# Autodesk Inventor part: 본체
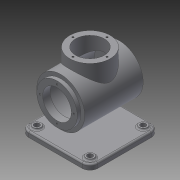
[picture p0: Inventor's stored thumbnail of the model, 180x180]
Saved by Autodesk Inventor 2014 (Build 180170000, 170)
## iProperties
Created: 2015-07
Part Number: 본체
Material: 일반
Document SubType Name: Modeling
Designer: basic
Density: 1 g/cm^3
Appearance: 기본값
Author: basic
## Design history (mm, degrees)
sketch "스케치1"
  geometry: L1 (-65, 65)-(65, 65); L2 (65, 65)-(65, -65); L3 (65, -65)-(-65, -65); L4 (-65, -65)-(-65, 65); L5 (-65, 65)-(65, -65); 2 further points
  constraints: 10 end point, 2 parallel, 1 coincident, 1 horizontal, 1 midpoint, 1 perpendicular
  dimensions: "d0" = 130 distance of L1.start L1.end; "d1" = 130 distance of L1.end L2.end
extrude "돌출1" new body sketch "스케치1" distance "d2" = 10; taper "d3" = 0 deg
fillet "모깎기1" dims "d4" = 15
fillet "모깎기2" dims "d5" = 3
sketch "스케치2"
  geometry: C1 r 7.5 at (-50, 50); 1 further point
  constraints: 1 centre point
  dimensions: "d6" = 50 horizontal distance of point (0, 0) C1.centre; "d7" = 50 horizontal distance of C1.centre point (0, 0); "d8" = 15 diameter of C1
extrude "돌출2" join sketch "스케치2" distance "d9" = 3; taper "d10" = 0 deg
sketch "스케치3"
  geometry: C1 r 7.5 at (0, 0) reference; C2 r 5 at (0, 0); 1 further point
  constraints: 1 centre point, 1 coincident
  dimensions: "d11" = 10 diameter of C2
extrude "돌출3" cut sketch "스케치3" stored distance "d12" = 3; taper "d13" = 0 deg
fillet "모깎기3" dims "d14" = 3
sketch "스케치4"
  geometry: L1 (-62, 10)-(62, 10) reference; L2 (65, 7)-(65, 0) reference; L3 (65, 0)-(-65, 0) reference; L4 (-65, 0)-(-65, 7) reference; L5 (0, 0)-(0, 78); C1 r 45 at (0, 78); A1 r 3 centre (62, 7) between (65, 7) and (62, 10) reference; A2 r 3 centre (-62, 7) between (-62, 10) and (-65, 7) reference
  constraints: 2 end point, 1 centre point, 1 coincident, 1 parallel
  dimensions: "d15" = 78 distance of L5.start L5.end; "d16" = 90 diameter of C1
extrude "돌출4" join sketch "스케치4" stored distance "d17" = 110; taper "d18" = 0 deg
sketch "스케치5"
  geometry: C1 r 45 at (0, 0) reference; C2 r 38 at (0, 0); 1 further point
  constraints: 1 centre point, 1 coincident
  dimensions: "d19" = 76 diameter of C2
extrude "돌출5" join sketch "스케치5" distance "d20" = 7; taper "d21" = 0 deg
sketch "스케치6"
  geometry: C1 r 38 at (0, 0) reference; 2 further points
  constraints: 1 vertical alignment
  dimensions: "d22" = 32 distance of C1.centre point (0, 32)
hole "구멍1" sketch "스케치6" at (0, 32) diameter "d23" = 3.242; stored, may be unused: countersink angle "d27" = 90 deg, drill point angle "d29" = 118 deg; dims "d24" = 8, "d25" = 4, "d26" = 2, "d28" = 10
sketch "스케치7"
  geometry: C1 r 38 at (0, 0) reference; C2 r 27 at (0, 0); 1 further point
  constraints: 1 centre point, 1 coincident
  dimensions: "d33" = 54 diameter of C2
extrude "돌출6" cut sketch "스케치7" distance "d34" = 14; taper "d35" = 0 deg
sketch "스케치8"
  geometry: C1 r 27 at (0, 0) reference; C2 r 40 at (0, 0); 1 further point
  constraints: 1 centre point, 1 coincident
  dimensions: "d36" = 80 diameter of C2
extrude "돌출7" cut sketch "스케치8" distance "d37" = 96; taper "d38" = 0 deg
node "작업 평면1"
sketch "스케치9"
  geometry: C1 r 38 at (0, 0); 1 further point
  constraints: 1 centre point, 1 coincident
  dimensions: "d40" = 76 diameter of C1
extrude "돌출8" join sketch "스케치9" stored distance "d41" = 96; taper "d42" = 0 deg
sketch "스케치10"
  geometry: C1 r 38 at (0, 0) reference; C2 r 27 at (0, 0)
  constraints: 1 centre point, 1 coincident
  dimensions: "d43" = 54 diameter of C2
extrude "돌출9" cut sketch "스케치10" stored distance "d44" = 96; taper "d45" = 0 deg
sketch "스케치11"
  geometry: C1 r 27 at (0, 0) reference; 1 further point
  constraints: 1 vertical alignment
  dimensions: "d46" = 32 distance of C1.centre point (0, 32)
hole "구멍2" sketch "스케치11" at (0, 32) diameter "d47" = 3.242; stored, may be unused: countersink angle "d51" = 90 deg, drill point angle "d53" = 118 deg; dims "d48" = 8, "d49" = 4, "d50" = 2, "d52" = 10
node "솔리드1"
mirror "대칭1"
mirror "대칭2"
pattern_circular "원형 패턴1" dims angle "d31" = 360 deg
pattern_circular "원형 패턴2" dims angle "d55" = 360 deg
node "절단 모서리 투영1"
